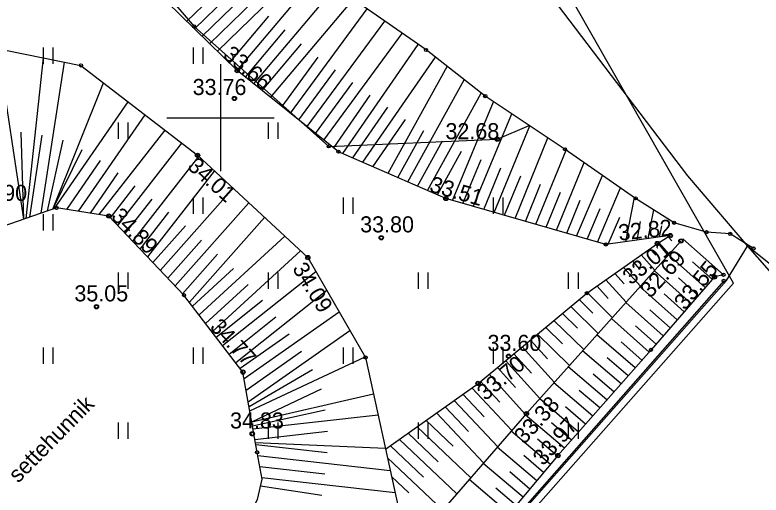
# Model space of a CAD drawing. Extents: x 641898 to 642452, y 6471715 to 6472255.
# Drawn here: x 642090.41 to 642125.22, y 6472132.39 to 6472154.8 of the extents above; entities that cross this region are included whole.
import ezdxf

# ---------------------------------------------------------------- set-up
doc = ezdxf.new("R2010")
doc.units = 0
for name, color, linetype in [('AED', 7, 'Continuous'), ('HALJASTUS', 7, 'Continuous'), ('KORGUS-EH2000', 7, 'Continuous'), ('MOOTMPUNKT', 7, 'Continuous'), ('MOOTPIIR', 7, 'Continuous'), ('PIIR', 7, 'Continuous'), ('RELJEEF', 7, 'Continuous'), ('VEEKOGU', 7, 'Continuous'), ('VORK', 7, 'Continuous')]:
    doc.layers.add(name, color=color, linetype=linetype)

msp = doc.modelspace()

# ---------------------------------------------------------------- linework, layer by layer
at = {"layer": 'AED'}
msp.add_lwpolyline([(642123.481, 6472142.39), (642081.315, 6472094.482), (642081.931, 6472094.059)], dxfattribs=at)
at = {"layer": 'HALJASTUS'}
for p, q in [((642091.725, 6472153.282), (642091.725, 6472152.521)), ((642092.18, 6472153.282), (642092.18, 6472152.521)), ((642098.725, 6472153.282), (642098.725, 6472152.521)), ((642099.18, 6472153.282), (642099.18, 6472152.521)), ((642095.225, 6472149.782), (642095.225, 6472149.021)), ((642095.68, 6472149.782), (642095.68, 6472149.021)), ((642102.225, 6472149.782), (642102.225, 6472149.021)), ((642102.68, 6472149.782), (642102.68, 6472149.021)), ((642098.725, 6472146.282), (642098.725, 6472145.521)), ((642099.18, 6472146.282), (642099.18, 6472145.521)), ((642105.725, 6472146.282), (642105.725, 6472145.521)), ((642106.18, 6472146.282), (642106.18, 6472145.521)), ((642112.725, 6472146.282), (642112.725, 6472145.521)), ((642113.18, 6472146.282), (642113.18, 6472145.521)), ((642091.725, 6472145.499), (642091.725, 6472144.738)), ((642092.18, 6472145.499), (642092.18, 6472144.738)), ((642095.225, 6472142.782), (642095.225, 6472142.021)), ((642095.68, 6472142.782), (642095.68, 6472142.021)), ((642102.225, 6472142.782), (642102.225, 6472142.021)), ((642102.68, 6472142.782), (642102.68, 6472142.021)), ((642109.225, 6472142.782), (642109.225, 6472142.021)), ((642109.68, 6472142.782), (642109.68, 6472142.021)), ((642116.225, 6472142.782), (642116.225, 6472142.021)), ((642116.68, 6472142.782), (642116.68, 6472142.021)), ((642091.725, 6472139.282), (642091.725, 6472138.521)), ((642092.18, 6472139.282), (642092.18, 6472138.521)), ((642098.725, 6472139.282), (642098.725, 6472138.521)), ((642099.18, 6472139.282), (642099.18, 6472138.521)), ((642105.725, 6472139.282), (642105.725, 6472138.521)), ((642106.18, 6472139.282), (642106.18, 6472138.521)), ((642112.725, 6472139.282), (642112.725, 6472138.521)), ((642113.18, 6472139.282), (642113.18, 6472138.521)), ((642095.225, 6472135.782), (642095.225, 6472135.021)), ((642095.68, 6472135.782), (642095.68, 6472135.021)), ((642102.225, 6472135.782), (642102.225, 6472135.021)), ((642102.68, 6472135.782), (642102.68, 6472135.021)), ((642109.225, 6472135.782), (642109.225, 6472135.021)), ((642109.68, 6472135.782), (642109.68, 6472135.021)), ((642116.225, 6472135.782), (642116.225, 6472135.021)), ((642116.68, 6472135.782), (642116.68, 6472135.021))]:
    msp.add_line(p, q, dxfattribs=at)
msp.add_lwpolyline([(642090.544, 6472184.173), (642089.776, 6472184.072), (642087.626, 6472183.976), (642087.514, 6472178.998), (642088.366, 6472174.432), (642089.975, 6472168.544), (642091.871, 6472163.809), (642094.517, 6472159.241), (642098.776, 6472154.266), (642105.061, 6472148.666), (642112.911, 6472148.999), (642114.406, 6472149.64)], dxfattribs=at)
at = {"layer": 'KORGUS-EH2000'}
for centre in [(642100.785, 6472152.198), (642100.654, 6472150.9), (642112.911, 6472148.999), (642098.936, 6472148.247), (642110.518, 6472146.231), (642094.79, 6472145.415), (642107.501, 6472144.4), (642120.985, 6472144.502), (642120.385, 6472144.131), (642121.483, 6472144.248), (642104.078, 6472143.474), (642123.047, 6472142.573), (642094.219, 6472141.18), (642113.441, 6472138.868), (642101.053, 6472138.133), (642112.021, 6472137.604), (642114.271, 6472136.19), (642101.484, 6472135.248), (642115.741, 6472134.233)]:
    msp.add_circle(centre, 0.1, dxfattribs=at)
at = {"layer": 'MOOTMPUNKT'}
for centre in [(642098.776, 6472154.266), (642109.59, 6472153.163), (642093.496, 6472152.442), (642100.785, 6472152.198), (642112.354, 6472151.011), (642100.654, 6472150.9), (642112.911, 6472148.999), (642105.061, 6472148.666), (642116.076, 6472148.525), (642098.936, 6472148.247), (642105.506, 6472148.417), (642110.518, 6472146.231), (642119.368, 6472146.237), (642092.349, 6472145.794), (642094.79, 6472145.415), (642121.165, 6472145.101), (642122.68, 6472144.661), (642107.501, 6472144.4), (642120.985, 6472144.502), (642123.778, 6472144.58), (642117.979, 6472144.088), (642120.385, 6472144.131), (642121.483, 6472144.248), (642124.862, 6472143.9), (642104.078, 6472143.474), (642123.047, 6472142.573), (642123.464, 6472142.672), (642123.481, 6472142.39), (642098.3, 6472141.719), (642117.097, 6472141.813), (642094.219, 6472141.18), (642120.087, 6472139.168), (642106.771, 6472138.81), (642113.441, 6472138.868), (642101.053, 6472138.133), (642112.021, 6472137.604), (642114.271, 6472136.19), (642101.484, 6472135.248), (642101.711, 6472134.384), (642115.741, 6472134.233)]:
    msp.add_circle(centre, 0.075, dxfattribs=at)
at = {"layer": 'MOOTPIIR'}
msp.add_lwpolyline([(642014.306, 6472085.384), (642027.67, 6472104.979), (642055.501, 6472084.843), (642081.563, 6472094.262), (642123.938, 6472142.273), (642065.721, 6472244.475), (642008.922, 6472196.948), (642003.347, 6472200.453), (641979.65, 6472162.756), (641979.65, 6472162.756), (641986.045, 6472158.736), (642004.269, 6472142.365), (641987.048, 6472123.488), (641970.482, 6472097.889), (641986.758, 6472084.396)], close=True, dxfattribs=at)
at = {"layer": 'PIIR'}
for p, q in [((642097, 6472179.89), (642121.79, 6472147.29)), ((642121.79, 6472147.29), (642124.59, 6472144.01)), ((642123.61, 6472142.4), (642124.59, 6472144.01)), ((642124.59, 6472144.01), (642126.14, 6472142.23)), ((642126.77, 6472142.26), (642124.59, 6472144.01)), ((642081.23, 6472094.44), (642123.61, 6472142.4))]:
    msp.add_line(p, q, dxfattribs=at)
at = {"layer": 'RELJEEF'}
for p, q in [((642098.426, 6472154.508), (642102.634, 6472158.584)), ((642099.141, 6472153.808), (642103.397, 6472157.932)), ((642099.856, 6472153.108), (642104.163, 6472157.281)), ((642100.778, 6472152.205), (642104.679, 6472156.842)), ((642098.783, 6472154.158), (642100.853, 6472156.163)), ((642101.558, 6472151.579), (642105.441, 6472156.195)), ((642102.339, 6472150.953), (642106.203, 6472155.547)), ((642099.498, 6472153.458), (642101.549, 6472155.445)), ((642103.266, 6472150.211), (642106.846, 6472155.082)), ((642100.42, 6472152.556), (642102.259, 6472154.742)), ((642104.047, 6472149.586), (642107.665, 6472154.509)), ((642101.168, 6472151.891), (642103.024, 6472154.098)), ((642104.828, 6472148.96), (642108.485, 6472153.936)), ((642101.949, 6472151.266), (642103.789, 6472153.454)), ((642090.831, 6472145.269), (642089.622, 6472153.225)), ((642105.712, 6472148.327), (642109.227, 6472153.417)), ((642090.933, 6472145.304), (642091.74, 6472152.797)), ((642102.875, 6472150.524), (642104.566, 6472152.825)), ((642106.646, 6472147.92), (642110.03, 6472152.821)), ((642091.642, 6472145.55), (642092.722, 6472152.599)), ((642107.818, 6472147.409), (642110.572, 6472152.399)), ((642103.656, 6472149.899), (642105.371, 6472152.232)), ((642108.739, 6472147.007), (642111.37, 6472151.777)), ((642092.175, 6472145.734), (642094.544, 6472151.634)), ((642104.437, 6472149.273), (642106.177, 6472151.64)), ((642105.288, 6472148.592), (642106.989, 6472151.056)), ((642109.659, 6472146.606), (642112.169, 6472151.155)), ((642092.262, 6472145.764), (642095.694, 6472150.747)), ((642110.829, 6472146.142), (642112.743, 6472150.751)), ((642106.179, 6472148.123), (642107.812, 6472150.488)), ((642093.386, 6472145.633), (642096.487, 6472150.136)), ((642111.797, 6472145.864), (642113.591, 6472150.185)), ((642107.113, 6472147.716), (642108.635, 6472149.92)), ((642112.764, 6472145.586), (642114.438, 6472149.619)), ((642090.831, 6472145.269), (642090.704, 6472149.333)), ((642094.347, 6472145.484), (642097.415, 6472149.42)), ((642108.278, 6472147.208), (642109.491, 6472149.405)), ((642091.108, 6472145.365), (642091.692, 6472149.181)), ((642091.938, 6472145.652), (642092.659, 6472148.959)), ((642109.199, 6472146.806), (642110.366, 6472148.922)), ((642113.743, 6472145.305), (642115.275, 6472149.06)), ((642095.214, 6472144.969), (642098.207, 6472148.809)), ((642092.175, 6472145.734), (642093.554, 6472148.515)), ((642110.119, 6472146.405), (642111.242, 6472148.439)), ((642114.709, 6472145.027), (642116.123, 6472148.492)), ((642092.838, 6472145.718), (642094.408, 6472147.999)), ((642095.91, 6472144.236), (642098.995, 6472148.193)), ((642111.313, 6472146.003), (642112.162, 6472148.049)), ((642115.676, 6472144.749), (642116.965, 6472147.907)), ((642112.28, 6472145.725), (642113.086, 6472147.666)), ((642093.934, 6472145.548), (642095.232, 6472147.431)), ((642096.606, 6472143.502), (642099.73, 6472147.51)), ((642113.248, 6472145.447), (642114.01, 6472147.283)), ((642116.617, 6472144.479), (642117.826, 6472147.308)), ((642114.226, 6472145.166), (642114.935, 6472146.904)), ((642094.866, 6472145.335), (642096.023, 6472146.82)), ((642097.198, 6472142.88), (642100.595, 6472146.707)), ((642115.193, 6472144.888), (642115.861, 6472146.526)), ((642117.586, 6472144.201), (642118.665, 6472146.726)), ((642095.562, 6472144.602), (642096.812, 6472146.206)), ((642116.16, 6472144.611), (642116.787, 6472146.149)), ((642118.912, 6472144.217), (642119.31, 6472146.277)), ((642097.889, 6472142.152), (642101.329, 6472146.026)), ((642096.258, 6472143.869), (642097.6, 6472145.591)), ((642117.102, 6472144.34), (642117.708, 6472145.759)), ((642119.958, 6472144.361), (642120.217, 6472145.7)), ((642098.551, 6472141.392), (642102.062, 6472145.346)), ((642118.088, 6472144.103), (642118.627, 6472145.366)), ((642119.435, 6472144.289), (642119.602, 6472145.153)), ((642096.852, 6472143.243), (642098.37, 6472144.954)), ((642120.482, 6472144.433), (642120.584, 6472144.963)), ((642099.004, 6472140.802), (642102.999, 6472144.476)), ((642120.886, 6472144.441), (642121.052, 6472144.257)), ((642097.543, 6472142.516), (642099.118, 6472144.29)), ((642120.453, 6472144.173), (642120.937, 6472143.638)), ((642123.46, 6472142.671), (642121.576, 6472144.351)), ((642099.615, 6472140.006), (642103.734, 6472143.793)), ((642120.038, 6472143.887), (642120.311, 6472143.586)), ((642098.235, 6472141.788), (642099.866, 6472143.626)), ((642119.627, 6472143.596), (642120.267, 6472142.889)), ((642122.619, 6472142.081), (642120.909, 6472143.606)), ((642118.803, 6472143.016), (642119.596, 6472142.14)), ((642119.215, 6472143.306), (642119.569, 6472142.914)), ((642122.947, 6472142.458), (642122.028, 6472143.278)), ((642098.698, 6472141.2), (642100.613, 6472142.961)), ((642100.104, 6472139.369), (642104.452, 6472142.826)), ((642118.392, 6472142.726), (642118.828, 6472142.243)), ((642121.963, 6472141.326), (642120.242, 6472142.861)), ((642117.98, 6472142.435), (642118.926, 6472141.391)), ((642122.291, 6472141.704), (642121.363, 6472142.532)), ((642099.31, 6472140.404), (642101.29, 6472142.225)), ((642100.713, 6472138.576), (642104.958, 6472141.95)), ((642117.568, 6472142.145), (642118.087, 6472141.572)), ((642121.307, 6472140.571), (642119.575, 6472142.116)), ((642117.122, 6472141.831), (642118.281, 6472140.671)), ((642121.635, 6472140.949), (642120.697, 6472141.785)), ((642099.799, 6472139.766), (642101.965, 6472141.488)), ((642116.734, 6472141.512), (642117.365, 6472140.88)), ((642120.651, 6472139.817), (642118.908, 6472141.371)), ((642101.106, 6472137.834), (642105.538, 6472140.945)), ((642116.347, 6472141.191), (642117.614, 6472139.925)), ((642120.979, 6472140.194), (642120.032, 6472141.039)), ((642100.408, 6472138.973), (642102.587, 6472140.705)), ((642115.961, 6472140.871), (642116.658, 6472140.174)), ((642119.994, 6472139.063), (642118.241, 6472140.626)), ((642115.173, 6472140.217), (642115.963, 6472139.455)), ((642115.56, 6472140.538), (642116.956, 6472139.19)), ((642120.323, 6472139.439), (642119.366, 6472140.292)), ((642100.916, 6472138.312), (642103.207, 6472139.92)), ((642101.296, 6472136.746), (642106.04, 6472140.076)), ((642114.785, 6472139.896), (642116.289, 6472138.445)), ((642119.35, 6472138.331), (642117.56, 6472139.865)), ((642114.46, 6472139.626), (642115.252, 6472138.751)), ((642119.664, 6472138.687), (642118.701, 6472139.546)), ((642114.075, 6472139.307), (642115.577, 6472137.649)), ((642101.201, 6472137.29), (642103.782, 6472139.101)), ((642101.37, 6472136.326), (642106.751, 6472138.845)), ((642113.689, 6472138.987), (642114.511, 6472138.08)), ((642118.689, 6472137.581), (642116.893, 6472139.119)), ((642113.304, 6472138.668), (642114.906, 6472136.9)), ((642119.02, 6472137.956), (642118.043, 6472138.792)), ((642101.336, 6472136.523), (642104.293, 6472138.246)), ((642112.919, 6472138.348), (642113.77, 6472137.409)), ((642118.028, 6472136.83), (642116.226, 6472138.374)), ((642112.534, 6472138.029), (642114.236, 6472136.15)), ((642118.359, 6472137.206), (642117.393, 6472138.033)), ((642112.128, 6472137.693), (642113.032, 6472136.734)), ((642117.367, 6472136.08), (642115.559, 6472137.629)), ((642101.46, 6472135.815), (642104.717, 6472137.341)), ((642101.46, 6472135.815), (642107.14, 6472137.122)), ((642111.313, 6472137.099), (642112.304, 6472136.048)), ((642111.724, 6472137.392), (642113.594, 6472135.409)), ((642117.698, 6472136.455), (642116.742, 6472137.274)), ((642110.902, 6472136.807), (642112.936, 6472134.649)), ((642116.706, 6472135.329), (642114.892, 6472136.884)), ((642110.491, 6472136.514), (642111.577, 6472135.362)), ((642117.037, 6472135.704), (642116.092, 6472136.514)), ((642101.494, 6472135.621), (642104.889, 6472136.364)), ((642101.519, 6472135.479), (642107.355, 6472136.14)), ((642110.08, 6472136.221), (642112.278, 6472133.89)), ((642116.049, 6472134.583), (642114.222, 6472136.133)), ((642109.591, 6472135.872), (642110.852, 6472134.674)), ((642116.376, 6472134.954), (642115.441, 6472135.755)), ((642101.605, 6472134.986), (642105.002, 6472135.37)), ((642109.176, 6472135.576), (642111.679, 6472133.198)), ((642115.398, 6472133.824), (642113.567, 6472135.377)), ((642108.761, 6472135.28), (642110.163, 6472133.949)), ((642115.719, 6472134.207), (642114.793, 6472134.993)), ((642101.63, 6472134.845), (642107.697, 6472134.574)), ((642101.647, 6472134.75), (642104.976, 6472134.377)), ((642107.932, 6472134.689), (642109.474, 6472133.224)), ((642108.347, 6472134.985), (642111.023, 6472132.442)), ((642114.757, 6472133.057), (642112.912, 6472134.622)), ((642101.738, 6472134.237), (642107.923, 6472133.543)), ((642107.795, 6472134.13), (642110.368, 6472131.685)), ((642115.078, 6472133.44), (642114.146, 6472134.231)), ((642101.833, 6472133.723), (642104.864, 6472133.383)), ((642114.115, 6472132.29), (642112.257, 6472133.866)), ((642107.985, 6472133.259), (642108.785, 6472132.499)), ((642114.436, 6472132.673), (642113.499, 6472133.468)), ((642101.929, 6472133.209), (642108.149, 6472132.511)), ((642113.473, 6472131.523), (642111.602, 6472133.11)), ((642101.873, 6472132.828), (642104.737, 6472132.391)), ((642113.794, 6472131.906), (642112.852, 6472132.706))]:
    msp.add_line(p, q, dxfattribs=at)
for points in [[(642120.985, 6472144.502), (642117.979, 6472144.088), (642110.518, 6472146.231), (642105.506, 6472148.417), (642100.785, 6472152.198), (642096.824, 6472156.077), (642094.039, 6472159.656), (642091.756, 6472163.65), (642090.992, 6472167.424), (642088.882, 6472176.556), (642088.445, 6472186.228), (642087.656, 6472194.367), (642088.054, 6472200.65), (642087.81, 6472201.434), (642086.987, 6472201.809), (642085.827, 6472201.697), (642084.8, 6472201.227), (642084.408, 6472200.976), (642075.818, 6472193.541), (642067.331, 6472185.862), (642054.685, 6472174.531), (642049.809, 6472171.194), (642046.347, 6472166.588), (642038.018, 6472156.193)], [(642088.203, 6472153.512), (642093.496, 6472152.442), (642098.936, 6472148.247), (642104.078, 6472143.474), (642106.771, 6472138.81), (642108.249, 6472132.052), (642108.153, 6472129.129), (642103.163, 6472123.369), (642094.632, 6472114.483), (642092.016, 6472113.081)], [(642101.723, 6472132.18), (642101.943, 6472133.131), (642101.711, 6472134.384), (642101.053, 6472138.133), (642098.3, 6472141.719), (642094.79, 6472145.415), (642092.349, 6472145.794), (642088.003, 6472144.291), (642078.92, 6472140.224), (642077.008, 6472138.651), (642077.72, 6472135.256), (642081.31, 6472131.799), (642085.536, 6472126.79), (642089.101, 6472122.158), (642091.173, 6472121.615), (642093.492, 6472122.583), (642097.061, 6472126.352), (642100.963, 6472131.23), (642101.467, 6472131.705), (642101.723, 6472132.18)], [(642107.707, 6472134.529), (642112.021, 6472137.604), (642117.097, 6472141.813), (642120.385, 6472144.131), (642120.985, 6472144.502)], [(642121.483, 6472144.248), (642114.271, 6472136.19), (642108.156, 6472129.132)], [(642123.464, 6472142.672), (642123.047, 6472142.573), (642120.087, 6472139.168), (642115.741, 6472134.233), (642111.73, 6472129.44), (642104.866, 6472121.549), (642098.208, 6472113.834), (642093.661, 6472110.303), (642090.857, 6472109.171), (642088.254, 6472108.802), (642086.484, 6472109.321), (642083.076, 6472111.816), (642080.848, 6472115.189), (642078.612, 6472117.548), (642074.153, 6472119.305), (642067.802, 6472127.345), (642067.041, 6472129.467)]]:
    msp.add_lwpolyline(points, dxfattribs=at)
at = {"layer": 'VEEKOGU'}
msp.add_lwpolyline([(642124.862, 6472143.9), (642123.778, 6472144.58), (642122.68, 6472144.661), (642121.165, 6472145.101), (642119.368, 6472146.237), (642116.076, 6472148.525), (642112.354, 6472151.011), (642109.59, 6472153.163), (642106.307, 6472155.459)], dxfattribs=at)
at = {"layer": 'VORK'}
for p, q in [((642100, 6472152.5), (642100, 6472147.5)), ((642097.5, 6472150), (642102.5, 6472150))]:
    msp.add_line(p, q, dxfattribs=at)

# ---------------------------------------------------------------- texts
at = {"layer": 'HALJASTUS'}
msp.add_text('settehunnik', height=0.75, rotation=45.4287, dxfattribs=at).set_placement((642090.568, 6472132.922))
at = {"layer": 'KORGUS-EH2000'}
for s, rotation, p in [('33.66', 319.9493, (642100.074, 6472152.854)), ('34.01', 318.0808, (642098.415, 6472147.669)), ('33.51', 343.9262, (642109.708, 6472146.569)), ('34.89', 314.4174, (642094.861, 6472145.356)), ('32.82', 5.8427, (642118.599, 6472144.264)), ('33.01', 39.3657, (642119.145, 6472142.163)), ('32.69', 47.4176, (642120.058, 6472141.542)), ('34.09', 301.3338, (642103.332, 6472142.966)), ('33.55', 51.1926, (642121.679, 6472140.977)), ('34.77', 312.7554, (642099.468, 6472140.203)), ('33.70', 40.2227, (642112.361, 6472136.762)), ('33.38', 47.3269, (642114.174, 6472134.724)), ('33.97', 48.6126, (642115.062, 6472133.72))]:
    msp.add_text(s, height=0.75, rotation=rotation, dxfattribs=at).set_placement(p)
for s, p in [('33.76', (642098.704, 6472151.061)), ('32.68', (642110.496, 6472148.998)), ('34.90', (642088.472, 6472146.119)), ('33.80', (642106.519, 6472144.65)), ('35.05', (642093.186, 6472141.43)), ('33.60', (642112.459, 6472139.118)), ('34.83', (642100.449, 6472135.498))]:
    msp.add_text(s, height=0.75, dxfattribs=at).set_placement(p)

doc.saveas('drawing.dxf')
